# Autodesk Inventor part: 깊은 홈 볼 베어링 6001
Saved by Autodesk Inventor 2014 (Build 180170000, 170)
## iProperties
Created: 2026-08
Part Number: 깊은 홈 볼 베어링 6001
Material: 강철, 연강
Document SubType Name: Modeling
Designer: dg
Density: 7.86 g/cm^3
Appearance: 강철
Mass: 21.4854 g
Surface Area: 31.1809 cm^2
Volume: 2.73351 cm^3
Author: jhkim
Description: 깊은 그루브 볼 베어링
Creation Date: 2026-07-31
Sending System: Autodesk Inventor 2027
Preprocessor: ST-DEVELOPER v20.1
Author: dg
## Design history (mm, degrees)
node "깊은 홈 볼 베어링 60011"
body "Solid1"
node "Solid1_1"
node "Solid1_2"
node "Solid1_3"
node "Solid1_4"
node "Solid1_5"
node "Solid1_6"
node "Solid1_7"
node "Solid1_8"
node "Solid1_9"
node "기준1"
node "기준2"
node "기준3"
node "기준4"
node "기준5"
node "기준6"
node "기준7"
node "기준8"
node "기준9"
node "기준10"
